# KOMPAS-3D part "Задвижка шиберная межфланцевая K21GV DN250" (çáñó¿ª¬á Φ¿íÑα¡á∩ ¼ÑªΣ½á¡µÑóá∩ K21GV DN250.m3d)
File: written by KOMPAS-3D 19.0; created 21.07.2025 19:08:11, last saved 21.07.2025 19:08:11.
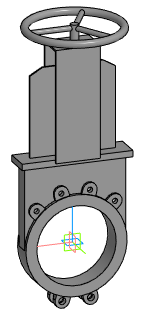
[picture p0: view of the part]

Document properties: Автор: Евгений; Полное имя файла: E:\Dendor Работа Сачек\3D для проектировщиков\2.3 Тип K21GV. Задвижка шиберная межфланцевая\stp_Задвижка шиберная K21GV DN50-400 с маховиком\Задвижка шиберная межфланцевая K21GV DN250.m3d

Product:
- Part/product: Задвижка шиберная межфланцевая K21GV DN250

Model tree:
1. Операция без истории:1  (labels: Задвижка шиберная межфланцевая K21GV DN250)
